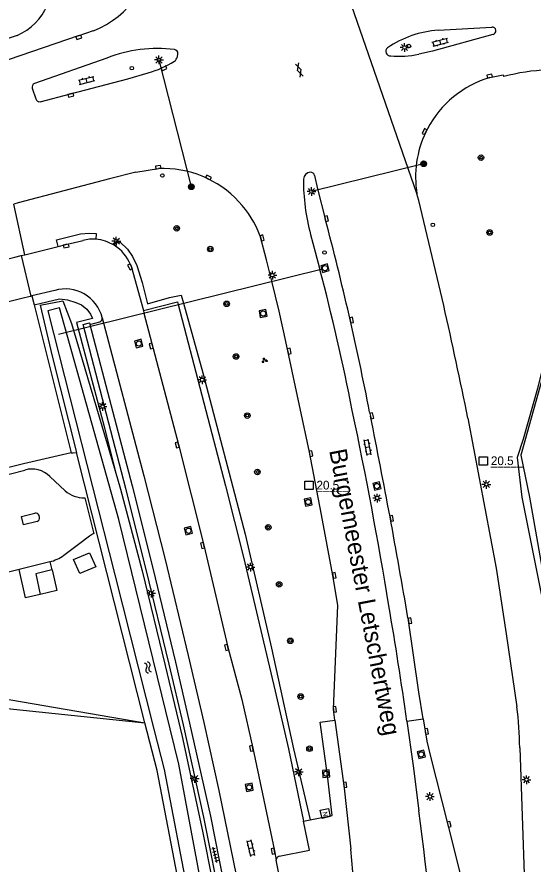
# Model space of a CAD drawing. Extents: x 124000 to 129000, y 395500 to 397503.
# Drawn here: x 124856.7 to 124930.7, y 396181.7 to 396303.2 of the extents above; entities that cross this region are included whole.
import ezdxf

# ---------------------------------------------------------------- set-up
doc = ezdxf.new("R2010")
doc.units = 0
for name, color, linetype in [('gg-afsc-draadraster', 7, 'Continuous'), ('gg-anno-openbare ruimte label', 7, 'Continuous'), ('gg-knt-verharding', 7, 'Continuous'), ('gg-knt-verharding nz', 7, 'Continuous'), ('gg-kntw-bovenkant insteek waterloop', 7, 'Continuous'), ('gg-kwrk-duiker nz buis', 7, 'Continuous'), ('gt-anno-nummer hm paal', 7, 'Continuous'), ('gt-grn-groengrens', 7, 'Continuous'), ('gt-grn-vlakafsluiter', 7, 'Continuous'), ('gt-grn-weggrens', 7, 'Continuous'), ('gt-knt-lijn portaal', 7, 'Continuous'), ('gt-symb-boom', 7, 'Continuous'), ('gt-symb-gesloten verharding', 7, 'Continuous'), ('gt-symb-groenvak', 7, 'Continuous'), ('gt-symb-hm paal', 7, 'Continuous'), ('gt-symb-klinker verharding', 7, 'Continuous'), ('gt-symb-kolk', 7, 'Continuous'), ('gt-symb-lichtmast', 7, 'Continuous'), ('gt-symb-nortonput', 7, 'Continuous'), ('gt-symb-portaalmast', 7, 'Continuous'), ('gt-symb-rioolschacht', 7, 'Continuous'), ('gt-symb-tegel verharding', 7, 'Continuous'), ('gt-symb-verkeersregelinstallatiepaal', 7, 'Continuous'), ('gt-symb-watersymbool', 7, 'Continuous'), ('gx-grn-maaiveld', 7, 'Continuous')]:
    doc.layers.add(name, color=color, linetype=linetype)

# ---------------------------------------------------------------- blocks, each defined once
blk = doc.blocks.new('gt0-KOLK')
at = {"layer": 'gt-symb-kolk'}
blk.add_lwpolyline([(0, 0), (0.38, 0), (0.38, 0.4), (-0.38, 0.4), (-0.38, 0), (0, 0)], dxfattribs=at)
blk = doc.blocks.new('gt0-VIPAAL')
at = {"layer": 'gt-symb-verkeersregelinstallatiepaal'}
blk.add_circle((0, 0), 0.25, dxfattribs=at)
blk = doc.blocks.new('gt0-KL1')
at = {"layer": 'gt-symb-klinker verharding'}
for p, q in [((-1.15, 0.3), (1.15, 0.3)), ((-1, -0.3), (-1, 0.3)), ((-0.5, 0.3), (-0.5, 0.45)), ((0, -0.3), (0, 0.3)), ((0.5, 0.3), (0.5, 0.45)), ((1, -0.3), (1, 0.3)), ((-1.15, -0.3), (1.15, -0.3)), ((-0.5, -0.45), (-0.5, -0.3)), ((0.5, -0.45), (0.5, -0.3))]:
    blk.add_line(p, q, dxfattribs=at)
blk = doc.blocks.new('gt0-PORTM')
at = {"layer": 'gt-symb-portaalmast'}
for radius in [0.4, 0.33, 0.27, 0.21, 0.15]:
    blk.add_circle((0, 0), radius, dxfattribs=at)
blk = doc.blocks.new('gt0-LMAST')
at = {"layer": 'gt-symb-lichtmast'}
for p, q in [((-0.18, 0.17), (-0.45, 0.44)), ((-0.01, 0.25), (-0.01, 0.62)), ((0.17, 0.17), (0.44, 0.44)), ((-0.26, 0), (-0.63, 0)), ((-0.18, -0.18), (-0.45, -0.45)), ((-0.01, -0.25), (-0.01, -0.63)), ((0.44, -0.45), (0.17, -0.18)), ((0.24, 0), (0.62, 0))]:
    blk.add_line(p, q, dxfattribs=at)
blk.add_circle((-0.01, 0), 0.25, dxfattribs=at)
blk = doc.blocks.new('gt0-GESVH1')
at = {"layer": 'gt-symb-gesloten verharding'}
for p, q in [((-0.99, -0.26), (0.01, 0.24)), ((0.01, -0.26), (-0.99, 0.24)), ((0.01, 0.24), (1.01, -0.26)), ((1.01, 0.24), (0.01, -0.26))]:
    blk.add_line(p, q, dxfattribs=at)
blk = doc.blocks.new('gt0-BOOM')
at = {"layer": 'gt-symb-boom'}
for radius in [0.4, 0.2]:
    blk.add_circle((0, 0), radius, dxfattribs=at)
blk = doc.blocks.new('gt0-RS')
at = {"layer": 'gt-symb-rioolschacht'}
blk.add_lwpolyline([(-0.5, -0.5), (0.5, -0.5), (0.5, 0.5), (-0.5, 0.5)], close=True, dxfattribs=at)
blk.add_circle((0, 0), 0.375, dxfattribs=at)
blk = doc.blocks.new('gt0-HMpaal')
at = {"layer": 'gt-symb-hm paal'}
blk.add_lwpolyline([(-0.6, 0.6), (0.6, 0.6), (0.6, -0.6), (-0.6, -0.6)], close=True, dxfattribs=at)
blk = doc.blocks.new('gt0-NPUT')
at = {"layer": 'gt-symb-nortonput'}
blk.add_lwpolyline([(-0.57, -0.61), (-0.57, 0.59), (0.63, 0.59), (0.63, -0.61)], close=True, dxfattribs=at)
blk.add_text('N', height=0.7, dxfattribs=at).set_placement((-0.22, -0.38))
blk = doc.blocks.new('gt0-GRVAK')
at = {"layer": 'gt-symb-groenvak'}
for p, q in [((-0.11, 0.19), (-0.23, 0.24)), ((-0.18, 0.15), (0.09, 0.15)), ((-0.09, 0.21), (-0.16, 0.32)), ((-0.05, 0.21), (-0.05, 0.39)), ((0, 0.21), (0.06, 0.32)), ((0.01, 0.19), (0.13, 0.24)), ((0.26, -0.05), (0.2, 0.06)), ((0.3, -0.05), (0.3, 0.13)), ((0.35, -0.05), (0.41, 0.06)), ((-0.25, -0.23), (-0.36, -0.18)), ((-0.32, -0.26), (-0.05, -0.26)), ((-0.23, -0.21), (-0.29, -0.09)), ((-0.18, -0.2), (-0.18, -0.02)), ((-0.14, -0.21), (-0.07, -0.09)), ((-0.12, -0.23), (0, -0.18)), ((0.24, -0.07), (0.12, -0.02)), ((0.17, -0.11), (0.44, -0.11)), ((0.37, -0.07), (0.49, -0.02))]:
    blk.add_line(p, q, dxfattribs=at)
blk = doc.blocks.new('gt0-TEG1')
at = {"layer": 'gt-symb-tegel verharding'}
for p, q in [((-1.12, 0), (1.13, 0)), ((-0.9, -0.25), (-0.9, 0.25)), ((-0.45, -0.25), (-0.45, 0.25)), ((0, -0.25), (0, 0.25)), ((0.45, -0.25), (0.45, 0.25)), ((0.9, -0.25), (0.9, 0.25))]:
    blk.add_line(p, q, dxfattribs=at)
blk = doc.blocks.new('gt0-WA')
at = {"layer": 'gt-symb-watersymbool'}
for centre, start, end in [((-0.32, 0.02), 28.0725, 151.9275), ((0.43, 0.42), 208.0725, 331.9275), ((-0.32, -0.43), 28.0725, 151.9275), ((0.43, -0.03), 208.0725, 331.9275)]:
    blk.add_arc(centre, 0.425, start, end, dxfattribs=at)

msp = doc.modelspace()

# ---------------------------------------------------------------- linework, layer by layer
at = {"layer": 'gg-afsc-draadraster'}
msp.add_lwpolyline([(124946.74, 396287.15), (124946.72, 396287.15), (124941.01, 396287.79), (124933.43, 396288.51), (124933.38, 396274.34), (124933.26, 396257.52), (124931.36, 396249.92), (124929.34, 396242.65), (124928.44, 396240.03), (124929.14, 396234.32), (124931.96, 396220.24), (124934.17, 396208.64), (124936.32, 396196.66), (124938.55, 396182.23), (124939.34, 396176.36)], dxfattribs=at)
at = {"layer": 'gg-knt-verharding'}
for p, q in [((124917.14, 396301.31), (124924.83, 396301.76)), ((124856.69, 396300.56), (124851.3, 396298.84)), ((124865.47, 396300.5), (124851.95, 396295.88)), ((124865.47, 396300.5), (124867.66, 396301.26)), ((124879.7, 396297.51), (124879.76, 396297.95)), ((124869.56, 396297.32), (124859.21, 396293.68)), ((124858.85, 396293), (124859.36, 396291.46)), ((124915.59, 396287.16), (124915.34, 396286.68)), ((124873.72, 396280.96), (124869.93, 396279.99)), ((124873.72, 396280.96), (124876.97, 396281.46)), ((124869.93, 396279.99), (124856.85, 396276.55)), ((124856.85, 396276.55), (124856.23, 396276.39)), ((124857.82, 396269.12), (124862.59, 396270.29)), ((124862.1, 396263.99), (124858.79, 396263.2)), ((124867.13, 396259.09), (124868.55, 396259.47)), ((124907.28, 396246.52), (124907.41, 396245.96)), ((124912.64, 396202.2), (124914.97, 396202.52)), ((124928.83, 396198.38), (124929.71, 396173.39)), ((124897.81, 396187.82), (124898.77, 396188.01)), ((124895.57, 396173.52), (124893.87, 396182.23))]:
    msp.add_line(p, q, dxfattribs=at)
for points in [[(124924.99, 396300.71), (124916.32, 396298.3), (124914.34, 396297.87)], [(124860.01, 396291.07), (124864.36, 396292.18), (124872.58, 396294.36), (124875.51, 396295.2)], [(124924.55, 396294.54), (124926.44, 396294.94), (124926.53, 396294.67)], [(124899.36, 396280.46), (124899.8, 396278.57), (124900.91, 396274.24)], [(124862.59, 396270.29), (124863.69, 396270.56), (124866.15, 396271.17)], [(124893.26, 396265.3), (124892.48, 396268.39), (124891.57, 396271.8)], [(124898.81, 396272.01), (124899.49, 396269.51), (124900.15, 396267.01)], [(124872.96, 396267.69), (124873.08, 396267.46), (124874.81, 396261.1)], [(124902.31, 396202.33), (124902.11, 396203.84), (124902.72, 396218.83), (124902.02, 396223.07), (124900.4, 396231.81), (124898.59, 396241.02), (124897.08, 396248.13), (124895.25, 396256.68), (124894.29, 396261), (124893.26, 396265.3)], [(124874.81, 396261.1), (124879.73, 396262.34), (124879.82, 396261.97)], [(124879.82, 396261.97), (124886.62, 396235.97), (124889.16, 396225.7), (124893.73, 396206.5), (124895.65, 396198.2), (124897.81, 396187.82)], [(124890.65, 396146.01), (124890.22, 396149.54), (124888.38, 396161.9), (124886.1, 396175.2), (124883.47, 396188.43), (124880.56, 396201.68), (124878.52, 396210.35), (124875.22, 396223.96), (124872.29, 396235.59), (124866.18, 396259.08), (124867.06, 396259.32), (124867.13, 396259.09)], [(124867.13, 396259.09), (124873.2, 396235.95), (124876.16, 396224.14), (124879.41, 396210.66), (124881.45, 396201.92), (124884.43, 396188.54), (124887.01, 396175.44), (124889.3, 396162.11), (124891.14, 396149.67), (124891.58, 396146.12)], [(124921.4, 396245.67), (124925.43, 396224.13), (124926.9, 396214.72), (124928.41, 396204.25)], [(124914.97, 396202.52), (124914.34, 396206.34), (124912.8, 396216.99)], [(124898.77, 396188.01), (124901.92, 396188.64), (124901.26, 396194.38), (124900.19, 396202.06), (124902.31, 396202.33)], [(124902.31, 396202.33), (124903.63, 396192.56), (124904.58, 396183.83)], [(124912.64, 396202.2), (124913.52, 396195.77), (124914.35, 396189.33)], [(124914.97, 396202.52), (124915.51, 396199.3), (124915.97, 396197.33), (124918.51, 396187.33), (124920.6, 396178.94), (124922.04, 396172.73), (124922.27, 396171.67), (124922.81, 396168.67), (124923.42, 396164.2), (124924.15, 396157.84), (124925.82, 396142.23)], [(124894.28, 396182.8), (124898.66, 396183.69), (124897.81, 396187.82)], [(124908.86, 396170.35), (124908.82, 396170.86), (124904.89, 396180.56), (124904.58, 396183.83)]]:
    msp.add_lwpolyline(points, dxfattribs=at)
for centre, radius, start, end in [((124862.76, 396313.7), 13.38, 291.4864, 0.9437), ((124853.22, 396308.39), 8.56, 293.8919, 17.6375), ((124924.88, 396301.23), 0.533, 282.5593, 95.3916), ((124918.11, 396286.73), 14.62, 93.8088, 124.3506), ((124876.83, 396278.73), 19.97, 82.9214, 111.3576), ((124879.22, 396298), 0.547, 354.6553, 82.381), ((124910.24, 396298.28), 0.64, 126.6594, 276.1157), ((124911.58, 396311.25), 13.66, 264.6509, 281.6506), ((124870.8, 396310.81), 16.31, 286.7833, 301.255), ((124878.68, 396297.75), 1.05, 303.5011, 346.4418), ((124933.75, 396268.01), 27.62, 91.9674, 105.1682), ((124928.7, 396280.36), 14.77, 106.3314, 152.6113), ((124859.39, 396293.15), 0.561, 109.2924, 195.5732), ((124859.89, 396291.62), 0.557, 196.7139, 282.4469), ((124928.55, 396280.3), 14.67, 154.2559, 189.5258), ((124877.65, 396266.7), 14.78, 42.6942, 92.6509), ((124898.84, 396279.88), 1.06, 92.2002, 175.9045), ((124898.84, 396280.42), 0.523, 5.2055, 94.1012), ((124928.94, 396279.93), 31.16, 179.9555, 194.7378), ((124192.54, 396097.03), 743.86, 11.52666, 14.07034), ((124878.15, 396266.88), 14.29, 20.1278, 43.5415), ((124508.87, 396169.46), 405.8, 10.9469, 14.9644), ((124867.54, 396265.46), 5.88, 85.5001, 103.6944), ((124867.54, 396265.49), 5.85, 58.2065, 85.4758), ((124867.54, 396265.49), 5.85, 22.1047, 58.242), ((124570.24, 396180.91), 340.97, 11.1329, 14.6261), ((124863.62, 396258.76), 5.45, 14.0839, 106.2091), ((124868.41, 396259.96), 0.511, 286.0141, 13.9149), ((124311.84, 396120.9), 606.16, 9.28866, 11.98276), ((123967.74, 396056.28), 958.62, 9.65138, 11.41232), ((124269.31, 396110.01), 649.9, 8.15493, 9.6309), ((124874.4, 396197.48), 54.44, 0.9468, 7.1426), ((123930.94, 396059.84), 991.89, 5.79289, 7.50114), ((124894.36, 396182.31), 0.5, 98.9171, 189.3131)]:
    msp.add_arc(centre, radius, start, end, dxfattribs=at)
at = {"layer": 'gg-knt-verharding nz'}
msp.add_line((124874.81, 396261.1), (124874.9, 396260.75), dxfattribs=at)
for points in [[(124874.9, 396260.75), (124879.85, 396241.86), (124883.51, 396227.44), (124886.93, 396212.81), (124888.94, 396205.3), (124890.51, 396198.32), (124891.92, 396191.76), (124893.62, 396183.57), (124893.87, 396182.23)], [(124868.9, 396260.08), (124874.86, 396237.39), (124877.92, 396225.38), (124881.23, 396211.59), (124883.48, 396201.98), (124885.66, 396192.24), (124888.56, 396177.99), (124891.04, 396163.88), (124893.12, 396149.83), (124893.61, 396145.92)]]:
    msp.add_lwpolyline(points, dxfattribs=at)
at = {"layer": 'gg-kntw-bovenkant insteek waterloop'}
for p, q in [((124859.99, 396261.87), (124861.72, 396254.54)), ((124861.72, 396254.54), (124865.22, 396240.73))]:
    msp.add_line(p, q, dxfattribs=at)
for points in [[(124937.05, 396269.31), (124928.97, 396240.36), (124930.22, 396234.34), (124932.7, 396220.22), (124935.34, 396208.63), (124937.37, 396196.85), (124939.32, 396182.16), (124940.08, 396176.33)], [(124859.99, 396261.87), (124863.25, 396262.52), (124864.5, 396259.24), (124870.78, 396238.1)], [(124870.78, 396238.1), (124871.55, 396235.48), (124874.62, 396223.74), (124877.94, 396210.17), (124880.4, 396199.97), (124883.3, 396186.4), (124886.08, 396172.43), (124888.33, 396158.61), (124888.88, 396154.72)]]:
    msp.add_lwpolyline(points, dxfattribs=at)
at = {"layer": 'gg-kwrk-duiker nz buis'}
msp.add_line((124862.64, 396257.72), (124900.54, 396267.1), dxfattribs=at)
at = {"layer": 'gt-grn-groengrens'}
for points in [[(124862.59, 396270.29), (124862.36, 396271.24), (124865.78, 396272.09), (124867.09, 396272.22), (124868.06, 396272.15), (124868, 396271.32)], [(124870.62, 396270.46), (124871.11, 396271.17), (124871.5, 396270.92), (124872.55, 396269.91), (124873.26, 396268.87), (124873.88, 396267.55), (124874.64, 396265.13), (124875.41, 396262.09), (124878.57, 396262.99), (124880.23, 396263.32), (124880.56, 396262.16)], [(124859.12, 396261.91), (124862.8, 396262.77), (124863.93, 396262.66), (124865.1, 396262.28), (124865.95, 396261.91), (124866.72, 396261.31), (124867.24, 396260.6), (124867.51, 396259.98), (124865.23, 396259.37), (124869.18, 396244.46), (124870.78, 396238.1)], [(124880.56, 396262.16), (124883.34, 396252.17), (124889.42, 396229.02), (124893.2, 396212.67), (124896.38, 396198.21), (124898.77, 396188.01)]]:
    msp.add_lwpolyline(points, dxfattribs=at)
at = {"layer": 'gt-grn-vlakafsluiter'}
msp.add_line((124857.82, 396269.12), (124856.23, 396276.39), dxfattribs=at)
at = {"layer": 'gt-grn-weggrens'}
msp.add_line((124914.08, 396277.88), (124900.25, 396317.66), dxfattribs=at)
at = {"layer": 'gt-knt-lijn portaal'}
for p, q in [((124881.7, 396278.86), (124877.06, 396297.06)), ((124915.03, 396282.16), (124898.94, 396278.18))]:
    msp.add_line(p, q, dxfattribs=at)
at = {"layer": 'gx-grn-maaiveld'}
for p, q in [((124857.26, 396268.99), (124857.82, 396269.12)), ((124857.26, 396268.99), (124858.66, 396263.17)), ((124858.66, 396263.17), (124858.79, 396263.2)), ((124858.79, 396263.2), (124859.12, 396261.91)), ((124859.12, 396261.91), (124864.46, 396240.7)), ((124875.04, 396201.96), (124865.22, 396240.73)), ((124841.36, 396234.03), (124857.8, 396238.22)), ((124861.39, 396237.3), (124863.57, 396235.25)), ((124866.39, 396234.24), (124867.7, 396229.09)), ((124859.91, 396231.44), (124859.85, 396231.69)), ((124861.4, 396225.04), (124856.99, 396223.95)), ((124861.4, 396225.04), (124861.7, 396223.89)), ((124856.99, 396223.95), (124843.52, 396220.62))]:
    msp.add_line(p, q, dxfattribs=at)
for points in [[(124805.45, 396255.91), (124822.11, 396260.15), (124840.01, 396264.65), (124856.36, 396268.76), (124857.26, 396268.99)], [(124839.18, 396258.37), (124857.77, 396262.96), (124858.16, 396263.06)], [(124858.16, 396263.06), (124858.57, 396263.15), (124858.66, 396263.17)], [(124886.93, 396154.39), (124884.39, 396171.95), (124879.89, 396196.02), (124871.27, 396231.11), (124862.76, 396261.49), (124861.11, 396261.08), (124870.72, 396223.16), (124876.33, 396201.03), (124877.81, 396195.26), (124881.39, 396176.52), (124885.07, 396154.08)], [(124779.43, 396242), (124784.63, 396233.59), (124791.04, 396219.98), (124795.64, 396213.28), (124798.84, 396210.68), (124802.85, 396209.48), (124875.04, 396201.96)], [(124779.43, 396242), (124805.87, 396213.81), (124875.04, 396201.96)], [(124864.46, 396240.7), (124857.6, 396239.09), (124841.12, 396234.98)], [(124864.46, 396240.7), (124864.74, 396240.71), (124865.22, 396240.73)], [(124859.56, 396230.85), (124857.61, 396230.34), (124857.3, 396231.56), (124859.24, 396232.04)], [(124867.06, 396228.73), (124865.49, 396227.55), (124863.38, 396225.98)], [(124865.68, 396223.37), (124864.8, 396225.4), (124867.1, 396226.34), (124867.98, 396224.34), (124865.68, 396223.37)], [(124860, 396220.37), (124857.88, 396219.87), (124856.99, 396223.95)], [(124861.7, 396223.89), (124859.36, 396223.35), (124860, 396220.37)], [(124861.7, 396223.89), (124861.74, 396223.9), (124862.39, 396220.92), (124860, 396220.37)], [(124884.14, 396153.93), (124880.35, 396176.66), (124876.77, 396195.12), (124875.04, 396201.96)]]:
    msp.add_lwpolyline(points, dxfattribs=at)
for centre, radius, start, end in [((124858.81, 396234.7), 3.66, 45.1232, 106.0096), ((124866.22, 396238.19), 3.96, 228.0186, 272.437), ((124859.37, 396231.56), 0.492, 15.0511, 104.8868), ((124859.45, 396231.31), 0.48, 282.8608, 15.3534), ((124871.05, 396222.42), 7.47, 116.6967, 122.3493), ((124859.74, 396231.09), 6.27, 285.3104, 305.4614)]:
    msp.add_arc(centre, radius, start, end, dxfattribs=at)

# ---------------------------------------------------------------- block references
at = {"layer": 'gt-symb-boom'}
for p in [(124923.27, 396283.04), (124879.6, 396272.9), (124924.51, 396272.3), (124884.42, 396269.92), (124886.76, 396262.06), (124888.12, 396254.51), (124889.73, 396246.03), (124891.18, 396237.94), (124892.74, 396230), (124894.3, 396221.82), (124895.91, 396213.72), (124897.39, 396205.72), (124898.66, 396198.23)]:
    msp.add_blockref('gt0-BOOM', p, dxfattribs=at)
at = {"layer": 'gt-symb-gesloten verharding', "rotation": -72.41690287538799}
msp.add_blockref('gt0-GESVH1', (124897.2, 396295.61), dxfattribs=at)
at = {"layer": 'gt-symb-groenvak'}
msp.add_blockref('gt0-GRVAK', (124892.17, 396253.95), dxfattribs=at)
at = {"layer": 'gt-symb-hm paal'}
for p in [(124923.61, 396239.53), (124898.58, 396236.03)]:
    msp.add_blockref('gt0-HMpaal', p, dxfattribs=at)
at = {"layer": 'gt-symb-klinker verharding'}
for p, rotation in [((124917.42, 396299.6), 14.425531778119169), ((124866.68, 396294.13), 14.42553178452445), ((124907.01, 396241.47), 101.00666417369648), ((124890.26, 396183.96), 104.06403671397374)]:
    msp.add_blockref('gt0-KL1', p, dxfattribs=dict(at, rotation=rotation))
at = {"layer": 'gt-symb-kolk'}
for p, rotation in [((124865.47, 396300.5), -160.85862620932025), ((124877.69, 396296.04), -154.9727212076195), ((124924.55, 396294.54), 11.950647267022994), ((124864.36, 396292.18), -165.6442150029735), ((124915.34, 396286.68), 62.56418149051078), ((124876.97, 396281.46), 8.85942931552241), ((124884.07, 396280.01), -25.719512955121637), ((124900.91, 396274.24), -75.40804379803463), ((124891.66, 396271.47), -74.39306952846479), ((124863.69, 396270.56), -166.227854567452), ((124873.08, 396267.46), 117.8972710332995), ((124904.51, 396259.69), -77.17287657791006), ((124876.12, 396256.07), 104.5919562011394), ((124895.55, 396255.23), -78.22937399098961), ((124907.41, 396245.96), -77.22875743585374), ((124879.85, 396241.86), 104.71731114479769), ((124898.67, 396240.54), -79.92566726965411), ((124910.26, 396231.24), -79.45426563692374), ((124883.51, 396227.44), 104.24474247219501), ((124902.02, 396223.07), -80.62242087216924), ((124912.87, 396216.56), -80.905195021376), ((124886.93, 396212.81), 103.17492660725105), ((124902.1, 396203.85), -81.9509382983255), ((124915.26, 396200.7), -80.27403432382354), ((124890.51, 396198.32), 102.1187603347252), ((124903.57, 396193.03), -82.59081596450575), ((124918.51, 396187.33), -75.9915565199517), ((124893.62, 396183.57), 100.43302473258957)]:
    msp.add_blockref('gt0-KOLK', p, dxfattribs=dict(at, rotation=rotation))
at = {"layer": 'gt-symb-lichtmast'}
for p in [(124912.3, 396298.85), (124877.06, 396297.06), (124898.94, 396278.18), (124870.94, 396271.07), (124893.34, 396266.18), (124883.27, 396251.17), (124868.97, 396247.34), (124924.04, 396236.16), (124908.37, 396234.2), (124890.2, 396224.3), (124875.94, 396220.56), (124882.18, 396193.95), (124897.11, 396194.93), (124929.81, 396193.79), (124915.95, 396191.37)]:
    msp.add_blockref('gt0-LMAST', p, dxfattribs=at)
at = {"layer": 'gt-symb-nortonput', "rotation": -76.75619797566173}
msp.add_blockref('gt0-NPUT', (124900.92, 396188.99), dxfattribs=at)
at = {"layer": 'gt-symb-portaalmast'}
for p in [(124915.03, 396282.16), (124881.7, 396278.86)]:
    msp.add_blockref('gt0-PORTM', p, dxfattribs=at)
at = {"layer": 'gt-symb-rioolschacht'}
for p, rotation in [((124900.88, 396267.19), 106.02410965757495), ((124892, 396260.68), -169.74640197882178), ((124874.15, 396256.37), -75.51896562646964), ((124908.34, 396235.92), 13.827795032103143), ((124898.46, 396233.64), -79.63367739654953), ((124881.28, 396229.51), 104.30027745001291), ((124914.69, 396197.42), 103.93901435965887), ((124901.04, 396194.66), 94.47340645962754), ((124890.01, 396192.7), -79.85920685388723)]:
    msp.add_blockref('gt0-RS', p, dxfattribs=dict(at, rotation=rotation))
at = {"layer": 'gt-symb-tegel verharding', "rotation": 104.06403671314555}
msp.add_blockref('gt0-TEG1', (124885.09, 396182.99), dxfattribs=at)
at = {"layer": 'gt-symb-verkeersregelinstallatiepaal'}
for p, rotation in [((124912.95, 396299.05), -73.5457897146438), ((124873.15, 396295.88), -73.54578971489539), ((124877.54, 396280.48), -73.5457897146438), ((124916.36, 396273.4), -73.54578971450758), ((124900.81, 396269.43), -73.54578971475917)]:
    msp.add_blockref('gt0-VIPAAL', p, dxfattribs=dict(at, rotation=rotation))
at = {"layer": 'gt-symb-watersymbool', "rotation": -68.71983368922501}
msp.add_blockref('gt0-WA', (124875.45, 396209.95), dxfattribs=at)

# ---------------------------------------------------------------- texts
at = {"layer": 'gg-anno-openbare ruimte label'}
msp.add_text('Burgemeester Letschertweg', height=2.5, rotation=280.8, dxfattribs=at).set_placement((124901.47, 396241.02))
at = {"layer": 'gt-anno-nummer hm paal'}
for p in [(124924.69, 396238.93), (124899.66, 396235.43)]:
    msp.add_text('20.5', height=1.25, dxfattribs=at).set_placement(p)
at = {"layer": 'gt-symb-hm paal'}
for p in [(124924.69, 396238.93), (124899.66, 396235.43)]:
    msp.add_text('_____', height=1.25, dxfattribs=at).set_placement(p)

doc.saveas('drawing.dxf')
